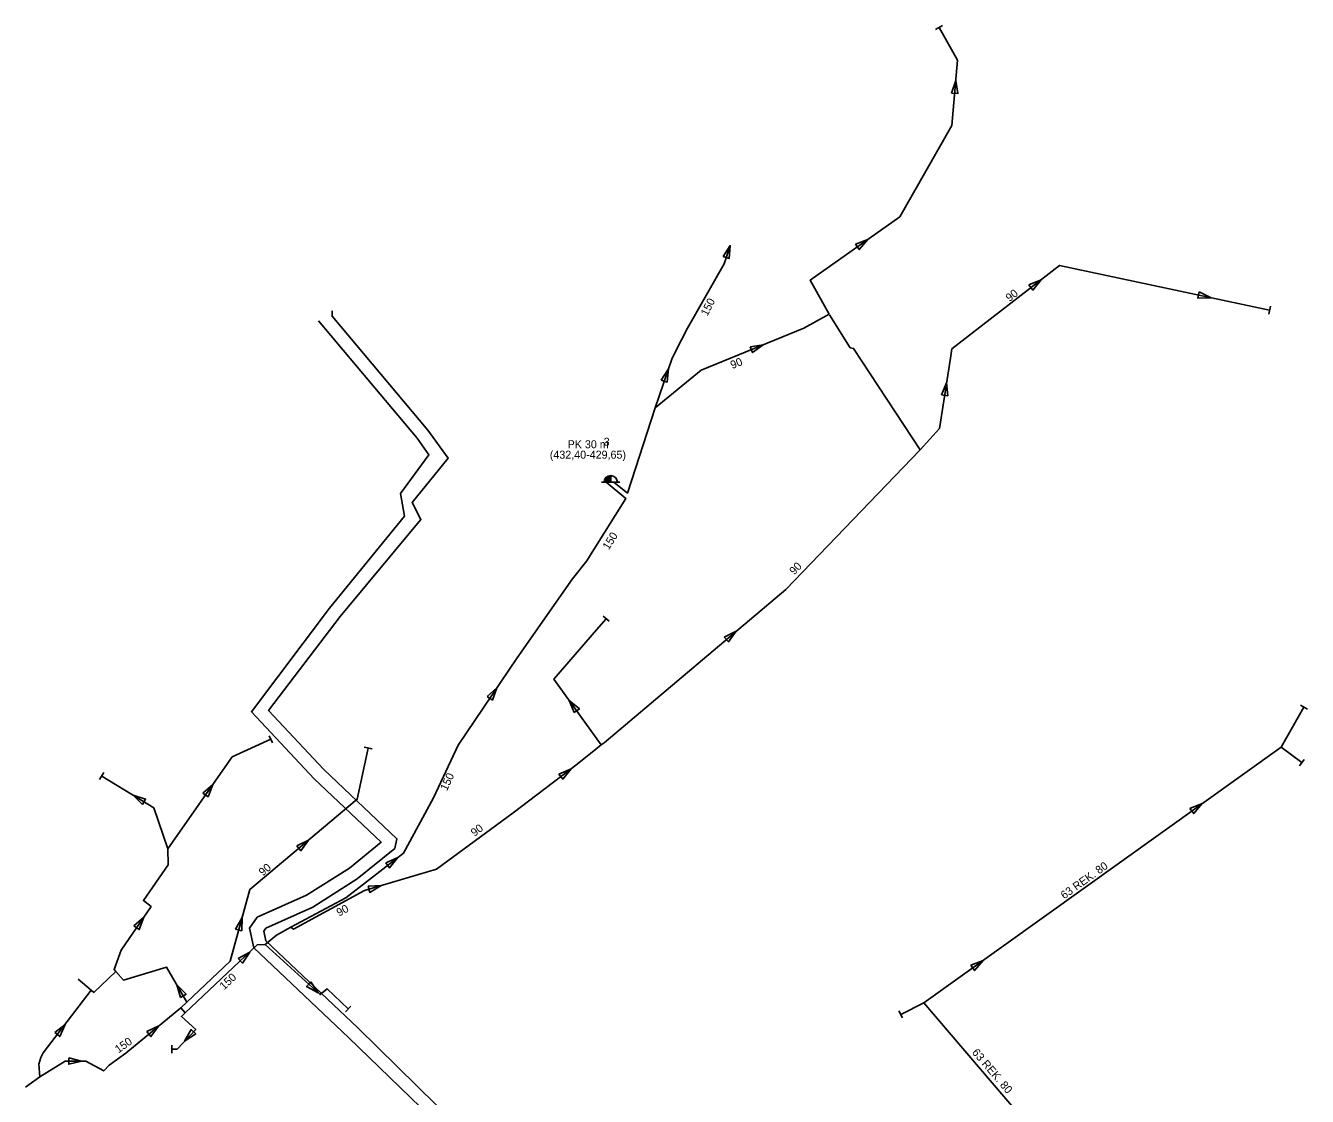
# Model space of a CAD drawing. Extents: x -444868 to -433212, y -1135421 to -1129859.
# Drawn here: x -442971 to -441370, y -1131197 to -1129859 of the extents above; entities that cross this region are included whole.
import ezdxf

# ---------------------------------------------------------------- set-up
doc = ezdxf.new("R2010")
doc.units = 0
for name, color, linetype in [('Vrstva 14', 7, 'Continuous'), ('Vrstva 3', 7, 'Continuous'), ('Vrstva 53', 7, 'Continuous')]:
    doc.layers.add(name, color=color, linetype=linetype)

msp = doc.modelspace()

# ---------------------------------------------------------------- linework, layer by layer
at = {"layer": 'Vrstva 14'}
for p, q in [((-442251.6, -1130429.5), (-442248.4, -1130429.5)), ((-442228.5, -1130429.5), (-442231.7, -1130429.5))]:
    msp.add_line(p, q, dxfattribs=at)
for points in [[(-442248.4, -1130429.5), (-442247.8, -1130426.3), (-442246, -1130423.5), (-442243.2, -1130421.7), (-442240, -1130421.1), (-442240, -1130429.5)], [(-442247.4, -1130428.7), (-442247, -1130426.6), (-442245.4, -1130424.1), (-442242.9, -1130422.5), (-442240.8, -1130422.1), (-442240.8, -1130428.7)], [(-442246.5, -1130427.9), (-442246.3, -1130426.9), (-442244.8, -1130424.7), (-442242.6, -1130423.2), (-442241.6, -1130423), (-442241.6, -1130427.9)], [(-442244.2, -1130425.3), (-442242.4, -1130424.1), (-442242.4, -1130427.1), (-442245.4, -1130427.1)], [(-442243.9, -1130426.3), (-442243.6, -1130425.9), (-442243.2, -1130425.6), (-442243.2, -1130426.3)]]:
    msp.add_lwpolyline(points, close=True, dxfattribs=at)
msp.add_lwpolyline([(-442240, -1130421.1), (-442236.8, -1130421.7), (-442234.1, -1130423.5), (-442232.3, -1130426.3), (-442231.7, -1130429.5), (-442240, -1130429.5)], dxfattribs=at)
at = {"layer": 'Vrstva 3'}
for p, q in [((-441825.4, -1129858.8), (-441834.1, -1129863.7)), ((-441416, -1130209.6), (-441418.1, -1130219.4)), ((-442241.9, -1130603.2), (-442249.5, -1130596.8)), ((-441369.8, -1130712.9), (-441378.5, -1130708)), ((-442666.8, -1130746.2), (-442662.7, -1130755.3)), ((-442538, -1130762.7), (-442547.8, -1130760.6)), ((-441373.6, -1130775.9), (-441379.6, -1130783.9)), ((-442873.3, -1130792.4), (-442878.5, -1130800.9)), ((-442564.6, -1131084.1), (-442571.5, -1131091.3)), ((-441880, -1131090), (-441875.6, -1131099)), ((-442788.2, -1131133), (-442788.2, -1131143))]:
    msp.add_line(p, q, dxfattribs=at)
for points in [[(-442184.6, -1130336.3), (-442127.1, -1130289.5), (-441998.7, -1130236.9), (-441967.2, -1130219.2), (-441990.9, -1130177.1), (-441878.7, -1130097.6), (-441813.7, -1129983.6), (-441806.9, -1129901.8), (-441829.8, -1129861.2)], [(-442184.6, -1130336.3), (-442163.2, -1130274.4), (-442151.5, -1130251.4), (-442144.3, -1130236.8), (-442098.5, -1130156.4), (-442090.6, -1130133.6)], [(-442639.4, -1130985.4), (-442636.3, -1130987.9), (-442547.5, -1130939.8), (-442457.6, -1130913.1), (-442361.8, -1130842.5), (-442282, -1130781.8), (-442258.5, -1130763), (-442251.9, -1130757.7), (-442248.4, -1130755), (-442021.4, -1130563.5), (-441853.6, -1130388.9), (-441829.4, -1130362.1), (-441815.6, -1130274.2), (-441814.1, -1130262.8), (-441679.4, -1130158.4), (-441417.1, -1130214.5)], [(-441853.6, -1130388.9), (-441936.6, -1130262.2), (-441940.7, -1130261.3), (-441966.7, -1130220.1)], [(-442236.2, -1130429.5), (-442219.2, -1130443.1), (-442184.6, -1130336.3)], [(-442671.5, -1131007), (-442657.4, -1130995.3), (-442639.4, -1130985.4), (-442570.9, -1130948.8), (-442498.9, -1130893), (-442461.4, -1130823.8), (-442430.7, -1130757.9), (-442356.7, -1130648.8), (-442287.9, -1130550.1), (-442269.9, -1130527.5), (-442261.2, -1130513.6), (-442221.3, -1130449.6), (-442245.6, -1130429.5)], [(-442251.9, -1130757.7), (-442311, -1130675.5), (-442257.6, -1130614.1), (-442245.7, -1130600)], [(-442119.6, -1132140.9), (-442065.9, -1132101.8), (-442033.1, -1132054.2), (-442004, -1132036.6), (-442015, -1132016.8), (-441941.6, -1131965.1), (-441917.7, -1131933.9), (-441875.7, -1131929.5), (-441753.9, -1131868.4), (-441718.6, -1131855.1), (-441685, -1131829.8), (-441675, -1131822.5), (-441653.8, -1131830.7), (-441635.2, -1131794.8), (-441617.7, -1131776.6), (-441796.3, -1131644.7), (-441736.6, -1131469.8), (-441641.2, -1131291.5), (-441712.2, -1131239.9), (-441848.9, -1131080.2), (-441402.5, -1130760.5), (-441374.1, -1130710.5)], [(-442970.9, -1131185.5), (-442953.1, -1131172.7), (-442921.4, -1131152.8), (-442895.5, -1131153.1), (-442873.4, -1131165.1), (-442866.7, -1131157.8), (-442845.8, -1131143.1), (-442776.9, -1131086.3), (-442769.4, -1131079.1), (-442715.4, -1131027.9), (-442691, -1130938.5), (-442556.7, -1130825.7), (-442542.9, -1130761.7)], [(-442858.4, -1131041), (-442860.4, -1131038.3), (-442851.4, -1131014.1), (-442814.1, -1130959.8), (-442823.7, -1130952.3), (-442792.7, -1130907.4), (-442793.4, -1130887.6), (-442712.7, -1130772.7), (-442664.7, -1130750.7)], [(-441402.5, -1130760.5), (-441376.6, -1130779.9)], [(-442793.4, -1130887.6), (-442810.6, -1130836.4), (-442875.9, -1130796.7)], [(-442776.9, -1131086.3), (-442771.6, -1131092.5), (-442681.5, -1131007.7), (-442671.5, -1131007), (-442603.1, -1131069.7), (-442594.4, -1131062.6), (-442568.1, -1131087.7)], [(-442953.1, -1131172.7), (-442954.3, -1131156.8), (-442952, -1131148.3), (-442948.8, -1131142.5), (-442888.9, -1131064.1), (-442885.5, -1131067.1), (-442858.4, -1131041), (-442848.8, -1131051.6), (-442794.8, -1131035.3), (-442769.4, -1131079.1)], [(-442905.1, -1131050.6), (-442888.9, -1131064.1)], [(-441848.9, -1131080.2), (-441877.8, -1131094.5)], [(-442771.6, -1131092.5), (-442776.3, -1131097.1), (-442758.4, -1131113.2), (-442781.8, -1131138), (-442788.2, -1131138)]]:
    msp.add_lwpolyline(points, dxfattribs=at)
for points in [[(-441814.3, -1129943.1), (-441806.3, -1129943.7), (-441809, -1129927.4)], [(-442099.6, -1130147.4), (-442092.1, -1130150), (-442090.6, -1130133.6)], [(-441934.2, -1130132.1), (-441929.6, -1130138.6), (-441918.9, -1130126.1)], [(-441717.6, -1130182.9), (-441712.7, -1130189.2), (-441702.5, -1130176.3)], [(-441504.9, -1130191.6), (-441506.6, -1130199.5), (-441490.1, -1130198.9)], [(-442065.7, -1130260.1), (-442062.7, -1130267.5), (-442049.4, -1130257.7)], [(-442176.9, -1130301.7), (-442169.3, -1130304.3), (-442167.9, -1130287.9)], [(-441826.9, -1130320.4), (-441819, -1130321.6), (-441820.5, -1130305.2)], [(-442098.1, -1130623), (-442092.9, -1130629.1), (-442083.3, -1130615.7)], [(-442394.4, -1130697.2), (-442387.8, -1130701.7), (-442382.1, -1130686.2)], [(-442285.7, -1130717.4), (-442279.2, -1130712.8), (-442291.8, -1130702.1)], [(-442304.8, -1130794.1), (-442300, -1130800.5), (-442289.6, -1130787.6)], [(-442749.4, -1130818), (-442742.9, -1130822.6), (-442736.9, -1130807.2)], [(-442825.1, -1130832.2), (-442821, -1130825.4), (-442836.7, -1130820.5)], [(-441516.4, -1130837.1), (-441511.7, -1130843.6), (-441501, -1130831)], [(-442632.3, -1130883.9), (-442627.1, -1130890), (-442617.4, -1130876.7)], [(-442521.1, -1130905.1), (-442516.2, -1130911.4), (-442506, -1130898.5)], [(-442543.2, -1130934.4), (-442540.9, -1130942), (-442526.7, -1130933.6)], [(-442835.6, -1130983.9), (-442829, -1130988.5), (-442823.2, -1130973)], [(-442708.6, -1130987.8), (-442700.9, -1130989.9), (-442700.6, -1130973.4)], [(-442705.3, -1131024.6), (-442699.8, -1131030.4), (-442690.9, -1131016.6)], [(-441790.1, -1131033.2), (-441785.4, -1131039.7), (-441774.8, -1131027.1)], [(-442777.4, -1131073.3), (-442770.4, -1131069.3), (-442781.9, -1131057.4)], [(-442614.5, -1131053.8), (-442619.9, -1131059.7), (-442605.4, -1131067.5)], [(-442934.6, -1131117.3), (-442928.3, -1131122.2), (-442921.7, -1131107)], [(-442819.3, -1131116.1), (-442814.3, -1131122.3), (-442804.5, -1131109)], [(-442758.4, -1131119), (-442764.2, -1131113.5), (-442772.3, -1131127.9)], [(-442917.1, -1131148.8), (-442917.1, -1131156.8), (-442901.1, -1131153)]]:
    msp.add_lwpolyline(points, close=True, dxfattribs=at)
at = {"layer": 'Vrstva 53'}
for points in [[(-442587.9, -1130215.1), (-442588.1, -1130221.7), (-442468.6, -1130364.2), (-442443.1, -1130399.2), (-442488, -1130454.9), (-442477.1, -1130475.9), (-442578.1, -1130597.2), (-442667.3, -1130714.7), (-442598.4, -1130788.3), (-442507.1, -1130875), (-442509.7, -1130887), (-442556.7, -1130925.3), (-442612.1, -1130960.5), (-442670.7, -1130986.7), (-442673.4, -1130990.4), (-442670.7, -1131002.7), (-442555.9, -1131111.4), (-442408.1, -1131256.6)], [(-442412.9, -1131272.8), (-442567.5, -1131123.6), (-442686, -1131011.3), (-442691.4, -1130986.6), (-442681.6, -1130973.1), (-442620.1, -1130945.7), (-442566.5, -1130911.7), (-442526.9, -1130879.4), (-442610.3, -1130800.2), (-442688.8, -1130716.2), (-442591.3, -1130586.8), (-442497.8, -1130471.7), (-442502.6, -1130443.6), (-442467.1, -1130395.4), (-442482, -1130374.4), (-442605, -1130227.7)]]:
    msp.add_lwpolyline(points, dxfattribs=at)

# ---------------------------------------------------------------- texts
at = {"layer": 'Vrstva 14'}
for s, p in [('      PK 30 m', (-442316.1, -1130387)), ('3', (-442248.8, -1130383.8)), ('(432,40-429,65)', (-442316.1, -1130400))]:
    msp.add_text(s, height=10, dxfattribs=at).set_placement(p)
at = {"layer": 'Vrstva 3'}
for s, rotation, p in [('150', 63.0975, (-442119.3, -1130222.6)), ('90', 37.7994, (-441741.9, -1130204.3)), ('90', 22.2961, (-442088.1, -1130288.1)), ('150', 58.0582, (-442242.5, -1130514.8)), ('90', 46.1448, (-442010.8, -1130545.9)), ('150', 64.9502, (-442444.6, -1130815.9)), ('90', 37.2761, (-442410.1, -1130872.7)), ('90', 40.0389, (-442674.6, -1130922.1)), ('63 REK. 80', 35.6148, (-441673.5, -1130950.9)), ('90', 28.4546, (-442579.3, -1130972.4)), ('150', 43.2543, (-442723, -1131064.6)), ('150', 35.09, (-442855, -1131143.4)), ('63 REK. 80', 310.5411, (-441789.3, -1131142.5))]:
    msp.add_text(s, height=10, rotation=rotation, dxfattribs=at).set_placement(p)

doc.saveas('drawing.dxf')
